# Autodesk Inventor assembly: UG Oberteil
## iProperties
Created: 2012-10
Part Number: UG Oberteil
Document SubType Name: Assembly
Designer: WH
Author: WH
ipwModelExtentsX: 400
ipwModelExtentsY: 95
ipwModelExtentsZ: 315
ipwMass: 6.3
ipwArea: 0.4 m^2
ipwVolume: 6.3
